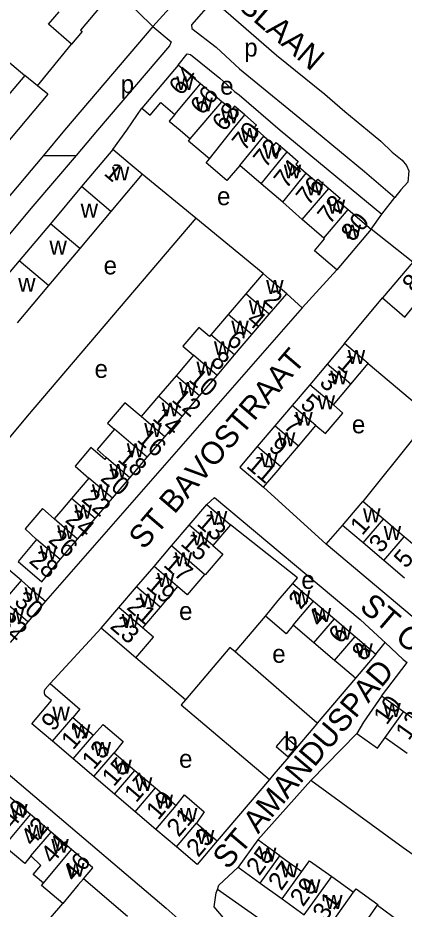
# Model space of a CAD drawing. Extents: x 161258 to 163262, y 380749 to 382054.
# Drawn here: x 163052.1 to 163137.8, y 381577.4 to 381774.9 of the extents above; entities that cross this region are included whole.
import ezdxf

# ---------------------------------------------------------------- set-up
doc = ezdxf.new("R2010")
doc.units = 0
for name, color, linetype in [('BLT_Basislijn', 7, 'Continuous'), ('BLT_Bebouwing', 7, 'Continuous'), ('BLT_Centroide', 7, 'Continuous'), ('BLT_Huisnummer', 7, 'Continuous'), ('BLT_Huisnummer_ tussenligend', 7, 'Continuous'), ('BLT_Huisnummer_reeks', 7, 'Continuous'), ('BLT_Onderverdeling_panden', 7, 'Continuous'), ('BLT_Straatnaam', 7, 'Continuous'), ('BLT_Vlakafsluiter', 7, 'Continuous')]:
    doc.layers.add(name, color=color, linetype=linetype)

msp = doc.modelspace()

# ---------------------------------------------------------------- linework, layer by layer
at = {"layer": 'BLT_Basislijn'}
for p, q in [((163082.1, 381773.01), (163062.51, 381750)), ((163056.49, 381759.86), (163064.05, 381769.1)), ((163056.49, 381759.86), (163053.66, 381762.17)), ((163076.29, 381750), (163079.64, 381754.92)), ((163073.21, 381745.74), (163076.29, 381750)), ((163110.33, 381750), (163132.89, 381731.38)), ((163091.57, 381730.53), (163079.73, 381740.25)), ((163132.89, 381731.38), (163135.76, 381735.11)), ((163130.52, 381728.08), (163132.89, 381731.38)), ((163106.52, 381718.25), (163091.57, 381730.53)), ((163122.86, 381719.1), (163115.21, 381710.67)), ((163115.21, 381710.67), (163111.75, 381713.79)), ((163124.6, 381702.75), (163133, 381712.84)), ((163115.21, 381710.67), (163058.25, 381645.7)), ((163140.28, 381682.2), (163128.63, 381667.72)), ((163106.61, 381670.89), (163120.49, 381658.28)), ((163052.93, 381650.24), (163035.79, 381664.62)), ((163120.49, 381658.28), (163124.16, 381662.45)), ((163157.28, 381627.33), (163120.49, 381658.28)), ((163100.33, 381634.42), (163107.05, 381642.35)), ((163131.54, 381633.92), (163133.58, 381636.48)), ((163118.54, 381618.64), (163100.33, 381634.42)), ((163089.35, 381623.83), (163078.31, 381633.09)), ((163132.79, 381624.62), (163138.48, 381632.04)), ((163127, 381628.59), (163118.54, 381618.64)), ((163118.36, 381618.43), (163111.77, 381610.66)), ((163118.54, 381618.64), (163118.36, 381618.43)), ((163127.31, 381616.36), (163117.14, 381605.96)), ((163111.77, 381610.66), (163108.94, 381607.35)), ((163108.94, 381607.35), (163107.94, 381606.17)), ((163107.94, 381606.17), (163096.36, 381592.56)), ((163117.14, 381605.96), (163105.33, 381592.77)), ((163076.46, 381575.83), (163066.68, 381584.17)), ((163131.58, 381557.2), (163096.41, 381581.77)), ((163053.55, 381568.82), (163062.13, 381578.64))]:
    msp.add_line(p, q, dxfattribs=at)
for points in [[(163095.43, 381778.91), (163093.54, 381780.44), (163092.58, 381780.79), (163090.89, 381781.07), (163088.82, 381780.47), (163082.1, 381773.01)], [(163095.43, 381778.91), (163090.68, 381773.39), (163090.73, 381772.59), (163096.09, 381768.42), (163101.32, 381763.61), (163117.91, 381750)], [(163095.43, 381778.91), (163109.51, 381766.65), (163120.22, 381758.01), (163124.63, 381754.13), (163129.71, 381750)], [(163082.1, 381773.01), (163086.11, 381769.6), (163085.79, 381768.74), (163069.79, 381750)], [(163087.72, 381764.46), (163089.7, 381766.95), (163090.43, 381766.83), (163096.96, 381761.57), (163100.18, 381758.6), (163101.23, 381757.89), (163110.33, 381750)], [(163058.77, 381757.99), (163056.49, 381759.86)], [(163058.77, 381757.99), (162989.39, 381675.54)], [(163062.51, 381750), (163057.84, 381744.45)], [(163069.79, 381750), (163065.05, 381744.45)], [(163117.91, 381750), (163129.03, 381740.88), (163135.76, 381735.11)], [(163129.71, 381750), (163132.65, 381747.6), (163135.16, 381745.16), (163137.36, 381743.36), (163138.32, 381742.17), (163138.87, 381740.99), (163138.61, 381738.52), (163137.07, 381736.82), (163135.76, 381735.11)], [(163065.05, 381744.45), (163055.44, 381733.2), (163000.14, 381667.02), (162999.88, 381666.79), (162998.67, 381667.15), (162995.32, 381669.95)], [(163057.84, 381744.45), (162995.82, 381670.75), (162995.32, 381669.95)], [(163091.57, 381730.53), (163054.18, 381686.63), (163035.79, 381664.62)], [(163129.85, 381698.3), (163143.79, 381686.55), (163140.28, 381682.2)], [(163094.05, 381667.08), (163095.74, 381668.66), (163128.05, 381641.63), (163132.92, 381637.09), (163133.58, 381636.48)], [(163113.11, 381649.61), (163114.13, 381650.83), (163099.29, 381662.59)], [(162982.59, 381655.68), (162982.92, 381655.96), (162983.14, 381656.6), (162984.49, 381658.12), (162987.04, 381658.99), (162989.05, 381658.78), (162990.32, 381658.03), (162999.22, 381650.31), (163015.1, 381637.09), (163026.02, 381627.75), (163057.87, 381600.69), (163085.05, 381577.63), (163092.33, 381571.16), (163092.65, 381569.57), (163088.3, 381564.95)], [(163059.27, 381627.39), (163070.61, 381639.68)], [(163133.58, 381636.48), (163137.6, 381632.77), (163138.48, 381632.04)], [(163100.33, 381634.42), (163099.17, 381635.43), (163089.35, 381623.83)], [(163089.35, 381623.83), (163088.38, 381622.7), (163107.94, 381606.17)], [(163149.49, 381582.65), (163137.61, 381591.03), (163117.14, 381605.96)], [(163096.41, 381581.77), (163096.73, 381582.74), (163100.99, 381586.72)], [(163193.8, 381513.79), (163189.45, 381511.89), (163188.37, 381511.64), (163185.43, 381513.57), (163146.25, 381541.52), (163123.46, 381557.34), (163122.6, 381558.15), (163097.75, 381575.47), (163095.67, 381577.96), (163096.15, 381581.02), (163096.41, 381581.77)]]:
    msp.add_lwpolyline(points, dxfattribs=at)
at = {"layer": 'BLT_Bebouwing'}
for p, q in [((163087.72, 381764.46), (163079.64, 381754.92)), ((163092.67, 381760.27), (163087.72, 381764.46)), ((163053.66, 381762.17), (163046.71, 381753.95)), ((163097.34, 381756.32), (163092.67, 381760.27)), ((163088.11, 381750), (163090.37, 381748.08)), ((163105.19, 381750), (163106.68, 381748.71)), ((163073.21, 381745.74), (163066.28, 381737.52)), ((163106.12, 381738.14), (163101.38, 381742.18)), ((163079.73, 381740.25), (163072.79, 381732.03)), ((163066.28, 381737.52), (163059.35, 381729.3)), ((163110.87, 381734.09), (163106.12, 381738.14)), ((163115.19, 381730.2), (163110.87, 381734.09)), ((163072.79, 381732.03), (163065.86, 381723.81)), ((163125.38, 381732.46), (163130.52, 381728.08)), ((163059.35, 381729.3), (163052.41, 381721.08)), ((163119.97, 381726.12), (163115.19, 381730.2)), ((163130.52, 381728.08), (163122.86, 381719.1)), ((163065.86, 381723.81), (163058.92, 381715.59)), ((163052.41, 381721.08), (163045.48, 381712.86)), ((163139.76, 381720.75), (163133, 381712.84)), ((163106.52, 381718.25), (163102.67, 381713.73)), ((163058.92, 381715.59), (163051.99, 381707.37)), ((163102.67, 381713.73), (163098.8, 381709.2)), ((163107.9, 381709.27), (163111.75, 381713.79)), ((163098.8, 381709.2), (163094.94, 381704.67)), ((163104.03, 381704.74), (163107.9, 381709.27)), ((163100.17, 381700.21), (163104.03, 381704.74)), ((163124.6, 381702.75), (163120.73, 381698.19)), ((163091.07, 381700.14), (163087.21, 381695.61)), ((163096.3, 381695.68), (163100.17, 381700.21)), ((163120.73, 381698.19), (163116.85, 381693.62)), ((163125.98, 381693.73), (163129.85, 381698.3)), ((163087.21, 381695.61), (163083.35, 381691.08)), ((163092.44, 381691.15), (163096.3, 381695.68)), ((163116.85, 381693.62), (163112.98, 381689.05)), ((163122.11, 381689.16), (163125.98, 381693.73)), ((163083.35, 381691.08), (163079.48, 381686.55)), ((163088.57, 381686.62), (163092.44, 381691.15)), ((163112.98, 381689.05), (163109.11, 381684.48)), ((163084.71, 381682.09), (163088.57, 381686.62)), ((163109.11, 381684.48), (163105.23, 381679.91)), ((163114.36, 381680.02), (163118.24, 381684.59)), ((163080.85, 381677.56), (163084.71, 381682.09)), ((163110.49, 381675.46), (163114.36, 381680.02)), ((163076.98, 381673.03), (163080.85, 381677.56)), ((163067.89, 381672.95), (163064.02, 381668.42)), ((163073.12, 381668.49), (163076.98, 381673.03)), ((163069.25, 381663.96), (163073.12, 381668.49)), ((163133.21, 381663.83), (163128.63, 381667.72)), ((163090.14, 381662.51), (163094.05, 381667.08)), ((163094.05, 381667.08), (163099.29, 381662.59)), ((163065.39, 381659.43), (163069.25, 381663.96)), ((163137.79, 381659.95), (163133.21, 381663.83)), ((163086.23, 381657.95), (163090.14, 381662.51)), ((163099.29, 381662.59), (163095.39, 381658.02)), ((163128.73, 381658.56), (163124.16, 381662.45)), ((163142.36, 381656.06), (163137.79, 381659.95)), ((163061.52, 381654.9), (163065.39, 381659.43)), ((163082.33, 381653.38), (163086.23, 381657.95)), ((163133.31, 381654.67), (163128.73, 381658.56)), ((163137.89, 381650.79), (163133.31, 381654.67)), ((163078.42, 381648.81), (163082.33, 381653.38)), ((163049.01, 381645.64), (163052.93, 381650.24)), ((163074.51, 381644.24), (163078.42, 381648.81)), ((163087.57, 381648.89), (163083.67, 381644.32)), ((163113.11, 381649.61), (163117.72, 381645.69)), ((163058.25, 381645.7), (163054.32, 381641.1)), ((163070.61, 381639.68), (163074.51, 381644.24)), ((163083.67, 381644.32), (163079.76, 381639.76)), ((163117.72, 381645.69), (163122.33, 381641.77)), ((163054.32, 381641.1), (163050.4, 381636.5)), ((163117.79, 381636.43), (163113.18, 381640.36)), ((163122.33, 381641.77), (163126.93, 381637.84)), ((163078.31, 381633.09), (163070.61, 381639.68)), ((163122.39, 381632.51), (163117.79, 381636.43)), ((163126.93, 381637.84), (163131.54, 381633.92)), ((163131.54, 381633.92), (163127, 381628.59)), ((163137.65, 381621.17), (163132.79, 381624.62)), ((163142.51, 381617.71), (163137.65, 381621.17)), ((163064.33, 381619.89), (163068.9, 381615.98)), ((163064.41, 381610.72), (163059.83, 381614.62)), ((163133.58, 381615.43), (163138.44, 381611.98)), ((163068.99, 381606.81), (163064.41, 381610.72)), ((163073.48, 381612.08), (163078.06, 381608.18)), ((163073.56, 381602.91), (163068.99, 381606.81)), ((163078.06, 381608.18), (163082.63, 381604.27)), ((163078.14, 381599), (163073.56, 381602.91)), ((163082.63, 381604.27), (163087.21, 381600.37)), ((163054.94, 381598.36), (163050.38, 381602.24)), ((163082.71, 381595.1), (163078.14, 381599)), ((163059.49, 381594.49), (163054.94, 381598.36)), ((163091.79, 381596.46), (163096.36, 381592.56)), ((163064.05, 381590.61), (163059.49, 381594.49)), ((163087.29, 381591.2), (163082.71, 381595.1)), ((163105.33, 381592.77), (163100.99, 381586.72)), ((163110.22, 381589.26), (163115.11, 381585.75)), ((163100.99, 381586.72), (163105.88, 381583.21)), ((163121.73, 381584.64), (163126.6, 381581.16)), ((163105.88, 381583.21), (163110.77, 381579.7)), ((163110.77, 381579.7), (163115.65, 381576.19))]:
    msp.add_line(p, q, dxfattribs=at)
for points in [[(163071.24, 381778.32), (163066.01, 381772.22), (163066.39, 381771.87), (163064.05, 381769.1)], [(163064.05, 381769.1), (163058.94, 381773.51), (163061.33, 381776.24)], [(163047.19, 381767.63), (163049.84, 381765.39), (163053.66, 381762.17)], [(163079.64, 381754.92), (163081.49, 381753.36), (163083.84, 381756.13), (163086.95, 381753.5)], [(163102.44, 381753.39), (163100.16, 381755.32), (163099.58, 381754.63), (163097.34, 381756.32)], [(163086.95, 381753.5), (163085.72, 381752.04), (163088.11, 381750)], [(163105.19, 381750), (163104.55, 381750.55), (163105.07, 381751.16), (163102.44, 381753.39)], [(163106.68, 381748.71), (163108.96, 381746.73), (163109.43, 381747.27), (163111.86, 381745.2)], [(163094.63, 381743.65), (163089.97, 381747.61), (163090.37, 381748.08)], [(163079.73, 381740.25), (163077.04, 381742.52), (163073.21, 381745.74)], [(163111.86, 381745.2), (163114.31, 381743.11), (163113.78, 381742.49), (163116.09, 381740.51)], [(163101.38, 381742.18), (163098.5, 381738.87), (163093.93, 381742.8), (163094.63, 381743.65)], [(163116.09, 381740.51), (163118.26, 381738.67), (163118.68, 381739.16), (163121.09, 381737.11)], [(163121.09, 381737.11), (163123.6, 381734.96), (163123.11, 381734.39), (163125.38, 381732.46)], [(163122.86, 381719.1), (163117.92, 381723.32), (163120.16, 381725.95), (163119.97, 381726.12)], [(163111.75, 381713.79), (163107.95, 381717.04), (163106.52, 381718.25)], [(163133, 381712.84), (163136.8, 381709.59), (163137.93, 381708.62), (163139.8, 381710.85)], [(163094.94, 381704.67), (163094.64, 381704.33), (163092.27, 381706.34), (163088.72, 381702.16), (163091.07, 381700.14)], [(163129.85, 381698.3), (163128.41, 381699.52), (163124.6, 381702.75)], [(163079.48, 381686.55), (163075.89, 381689.6), (163072.03, 381685.08), (163073.58, 381683.76)], [(163118.24, 381684.59), (163120.38, 381682.78), (163124.24, 381687.32), (163122.11, 381689.16)], [(163073.58, 381683.76), (163069.73, 381679.24), (163071.75, 381677.49)], [(163071.75, 381677.49), (163071.43, 381677.06), (163068.34, 381679.7), (163064.83, 381675.58), (163067.89, 381672.95)], [(163105.23, 381679.91), (163101.36, 381675.34), (163106.61, 381670.89)], [(163106.61, 381670.89), (163109.85, 381674.7), (163110.49, 381675.46)], [(163064.02, 381668.42), (163061.69, 381665.62), (163060.16, 381663.89)], [(163124.16, 381662.45), (163127.39, 381666.26), (163128.63, 381667.72)], [(163060.16, 381663.89), (163057.58, 381666.18), (163053.73, 381661.66), (163056.3, 381659.36)], [(163056.3, 381659.36), (163052.19, 381654.46), (163057.44, 381649.98), (163061.52, 381654.9)], [(163095.39, 381658.02), (163097.63, 381656.1), (163093.7, 381651.49), (163093.56, 381651.61)], [(163052.93, 381650.24), (163054.44, 381648.95), (163058.25, 381645.7)], [(163093.56, 381651.61), (163089.69, 381647.08), (163087.57, 381648.89)], [(163107.05, 381642.35), (163109.87, 381645.8), (163113.11, 381649.61)], [(163113.18, 381640.36), (163111.66, 381638.43), (163107.05, 381642.35)], [(163078.31, 381633.09), (163082.21, 381637.66), (163079.76, 381639.76)], [(163127, 381628.59), (163123.19, 381631.83), (163122.39, 381632.51)], [(163059.83, 381614.62), (163055.25, 381618.52), (163059.59, 381623.62), (163058.4, 381624.64), (163058.13, 381624.99), (163058.01, 381625.39), (163058.06, 381625.82), (163058.23, 381626.17), (163059.27, 381627.39)], [(163059.27, 381627.39), (163065.91, 381621.75), (163064.33, 381619.89)], [(163132.79, 381624.62), (163128.78, 381618.84), (163127.31, 381616.36)], [(163068.9, 381615.98), (163071.08, 381618.37), (163075.51, 381614.6), (163073.48, 381612.08)], [(163127.31, 381616.36), (163131.89, 381613.11), (163133.58, 381615.43)], [(163087.21, 381600.37), (163089.08, 381602.74), (163093.46, 381599.01), (163091.79, 381596.46)], [(163055.04, 381589.22), (163053.65, 381587.51), (163049.12, 381591.37), (163050.48, 381593.1)], [(163096.36, 381592.56), (163091.87, 381587.29), (163087.29, 381591.2)], [(163110.22, 381589.26), (163109.4, 381589.85), (163105.33, 381592.77)], [(163066.68, 381584.17), (163068.75, 381586.61), (163064.05, 381590.61)], [(163057.8, 381583.18), (163055.55, 381585.1), (163057.25, 381587.1), (163055.04, 381589.22)], [(163115.11, 381585.75), (163116.84, 381588.13), (163121.73, 381584.64)], [(163062.13, 381578.64), (163057.38, 381582.69), (163057.8, 381583.18)], [(163066.68, 381584.17), (163065.51, 381582.8), (163062.13, 381578.64)], [(163126.6, 381581.16), (163127.15, 381581.93), (163132, 381578.45), (163131.87, 381578.27)], [(163131.87, 381578.27), (163136.72, 381574.79), (163134.66, 381571.72)]]:
    msp.add_lwpolyline(points, dxfattribs=at)
msp.add_lwpolyline([(163111.33, 381615.7), (163109.41, 381613.47), (163112.09, 381611.17), (163114.02, 381613.38)], close=True, dxfattribs=at)
at = {"layer": 'BLT_Onderverdeling_panden'}
for p, q in [((163086.95, 381753.5), (163092.67, 381760.27)), ((163090.37, 381748.08), (163097.34, 381756.32)), ((163099.68, 381750), (163102.44, 381753.39)), ((163094.63, 381743.65), (163099.68, 381750)), ((163101.38, 381742.18), (163106.68, 381748.71)), ((163106.12, 381738.14), (163111.86, 381745.2)), ((163110.87, 381734.09), (163116.09, 381740.51)), ((163072.79, 381732.03), (163066.28, 381737.52)), ((163115.19, 381730.2), (163121.09, 381737.11)), ((163119.97, 381726.12), (163125.38, 381732.46)), ((163065.86, 381723.81), (163059.35, 381729.3)), ((163058.92, 381715.59), (163052.41, 381721.08)), ((163107.9, 381709.27), (163102.67, 381713.73)), ((163104.03, 381704.74), (163098.8, 381709.2)), ((163100.17, 381700.21), (163094.94, 381704.67)), ((163096.3, 381695.68), (163091.07, 381700.14)), ((163125.98, 381693.73), (163120.73, 381698.19)), ((163092.44, 381691.15), (163087.21, 381695.61)), ((163122.11, 381689.16), (163116.85, 381693.62)), ((163088.57, 381686.62), (163083.35, 381691.08)), ((163118.24, 381684.59), (163112.98, 381689.05)), ((163084.71, 381682.09), (163079.48, 381686.55)), ((163080.85, 381677.56), (163073.58, 381683.76)), ((163114.36, 381680.02), (163109.11, 381684.48)), ((163110.49, 381675.46), (163105.23, 381679.91)), ((163076.98, 381673.03), (163071.75, 381677.49)), ((163073.12, 381668.49), (163067.89, 381672.95)), ((163069.25, 381663.96), (163064.02, 381668.42)), ((163065.39, 381659.43), (163060.16, 381663.89)), ((163128.73, 381658.56), (163133.21, 381663.83)), ((163095.39, 381658.02), (163090.14, 381662.51)), ((163133.31, 381654.67), (163137.79, 381659.95)), ((163061.52, 381654.9), (163056.3, 381659.36)), ((163093.56, 381651.61), (163086.23, 381657.95)), ((163087.57, 381648.89), (163082.33, 381653.38)), ((163083.67, 381644.32), (163078.42, 381648.81)), ((163054.32, 381641.1), (163049.01, 381645.64)), ((163079.76, 381639.76), (163074.51, 381644.24)), ((163113.18, 381640.36), (163117.72, 381645.69)), ((163117.79, 381636.43), (163122.33, 381641.77)), ((163122.39, 381632.51), (163126.93, 381637.84)), ((163133.58, 381615.43), (163137.65, 381621.17)), ((163059.83, 381614.62), (163064.33, 381619.89)), ((163064.41, 381610.72), (163068.9, 381615.98)), ((163068.99, 381606.81), (163073.48, 381612.08)), ((163073.56, 381602.91), (163078.06, 381608.18)), ((163078.14, 381599), (163082.63, 381604.27)), ((163082.71, 381595.1), (163087.21, 381600.37)), ((163050.48, 381593.1), (163054.94, 381598.36)), ((163087.29, 381591.2), (163091.79, 381596.46)), ((163055.04, 381589.22), (163059.49, 381594.49)), ((163057.8, 381583.18), (163064.05, 381590.61)), ((163105.88, 381583.21), (163110.22, 381589.26)), ((163110.77, 381579.7), (163115.11, 381585.75)), ((163115.65, 381576.19), (163121.73, 381584.64)), ((163120.54, 381572.68), (163126.6, 381581.16)), ((163125.43, 381569.18), (163131.87, 381578.27))]:
    msp.add_line(p, q, dxfattribs=at)
at = {"layer": 'BLT_Vlakafsluiter'}
for p, q in [((163082.1, 381773.01), (163073.62, 381781.31)), ((163057.84, 381744.45), (163065.05, 381744.45)), ((163139.76, 381720.75), (163130.52, 381728.08))]:
    msp.add_line(p, q, dxfattribs=at)

# ---------------------------------------------------------------- texts
at = {"layer": 'BLT_Centroide'}
for s, p in [('p', (163102.34, 381766.34)), ('p', (163074.95, 381758.24)), ('w', (163087.27, 381758.91)), ('e', (163097, 381757.9)), ('w', (163091.53, 381754.19)), ('w', (163097.22, 381751.55)), ('w', (163101.61, 381747.42)), ('w', (163106.61, 381743.7)), ('w', (163073, 381738.89)), ('w', (163111.11, 381739.33)), ('w', (163116.11, 381735.56)), ('e', (163096.31, 381733.41)), ('w', (163066.06, 381730.67)), ('w', (163120.86, 381731.53)), ('w', (163124.39, 381726.02)), ('w', (163059.14, 381722.45)), ('e', (163071.15, 381718.07)), ('w', (163052.2, 381714.23)), ('w', (163107.2, 381713.75)), ('w', (163103.34, 381709.25)), ('w', (163099.48, 381704.72)), ('w', (163095.62, 381700.19)), ('w', (163125.29, 381698.25)), ('e', (163069.14, 381695.14)), ('w', (163091.75, 381695.66)), ('w', (163121.42, 381693.69)), ('w', (163087.89, 381691.12)), ('w', (163118.61, 381688.19)), ('w', (163084.03, 381686.59)), ('w', (163113.67, 381684.53)), ('e', (163126.21, 381682.86)), ('w', (163080.16, 381682.06)), ('w', (163109.8, 381679.97)), ('w', (163076.3, 381677.53)), ('w', (163105.92, 381675.41)), ('w', (163072.44, 381673)), ('w', (163068.56, 381668.47)), ('w', (163064.7, 381663.94)), ('w', (163094.72, 381662.56)), ('w', (163128.69, 381663.14)), ('w', (163060.84, 381659.41)), ('w', (163133.27, 381659.25)), ('w', (163090.81, 381658)), ('w', (163056.98, 381654.88)), ('w', (163086.91, 381653.41)), ('w', (163083, 381648.84)), ('e', (163115.01, 381648.39)), ('w', (163053.62, 381645.66)), ('w', (163113.14, 381644.98)), ('w', (163079.09, 381644.28)), ('w', (163049.7, 381641.06)), ('e', (163087.89, 381641.5)), ('w', (163117.75, 381641.06)), ('w', (163075.18, 381639.72)), ('w', (163122.36, 381637.14)), ('w', (163126.97, 381633.22)), ('e', (163108.55, 381632.02)), ('w', (163059.8, 381619.2)), ('w', (163133.19, 381620.03)), ('w', (163064.36, 381615.3)), ('b', (163111.2, 381612.59)), ('w', (163068.94, 381611.39)), ('w', (163073.52, 381607.48)), ('e', (163087.89, 381608.76)), ('w', (163078.09, 381603.58)), ('w', (163082.67, 381599.69)), ('w', (163050.44, 381597.67)), ('w', (163088.09, 381596.8)), ('w', (163054.3, 381592.97)), ('w', (163091.83, 381591.88)), ('w', (163059.55, 381589.91)), ('w', (163105.61, 381587.98)), ('w', (163063.06, 381584.61)), ('w', (163110.48, 381584.48)), ('w', (163115.38, 381580.97)), ('w', (163120.27, 381577.47))]:
    msp.add_text(s, height=4, dxfattribs=at).set_placement(p)
at = {"layer": 'BLT_Huisnummer'}
for s, rotation, p in [('64', 50.9195, (163088.37, 381757.48)), ('68', 50.921, (163097.93, 381749.51)), ('72', 50.9216, (163107.08, 381741.47)), ('76', 50.919, (163116.56, 381733.1)), ('80', 49.5327, (163126.44, 381725.1)), ('82', 49.4819, (163140.03, 381713.77)), ('2', 319.5363, (163106.36, 381712.13)), ('6', 319.5417, (163098.2, 381703.04)), ('1', 319.7143, (163122.73, 381697.75)), ('10', 319.5408, (163089.76, 381694.57)), ('5', 319.709, (163114.56, 381688.94)), ('14', 319.5398, (163081.78, 381685.97)), ('18', 319.5335, (163074.05, 381676.86)), ('11', 319.7099, (163102.6, 381675.39)), ('22', 319.5389, (163066.02, 381667.99)), ('13', 319.4581, (163091.61, 381662.63)), ('1', 49.662, (163128.51, 381660.06)), ('28', 319.5255, (163054.41, 381654.32)), ('5', 49.662, (163138.21, 381652.74)), ('17', 319.4581, (163084.22, 381653.48)), ('2', 49.5949, (163114.83, 381643.62)), ('30', 319.5427, (163051.1, 381645.25)), ('23', 319.4581, (163072.37, 381639.82)), ('8', 49.594, (163128.89, 381632.18)), ('10', 54.6176, (163133.94, 381618.04)), ('9', 49.5387, (163060, 381616.63)), ('13', 49.5333, (163068.98, 381608.13)), ('17', 49.5343, (163078.37, 381600.84)), ('40', 49.7593, (163050.98, 381595.02)), ('23', 49.5333, (163092.15, 381588.74)), ('25', 54.3353, (163105.68, 381584.63)), ('46', 49.5914, (163064.67, 381583.3)), ('29', 54.3371, (163115.4, 381577.79))]:
    msp.add_text(s, height=4, rotation=rotation, dxfattribs=at).set_placement(p)
at = {"layer": 'BLT_Huisnummer_ tussenligend'}
for s, rotation, p in [('66', 50.9195, (163093.11, 381753.17)), ('70', 50.921, (163102.37, 381745.2)), ('74', 50.9216, (163111.66, 381736.86)), ('78', 50.919, (163121.3, 381728.95)), ('4', 319.5363, (163102.62, 381707.55)), ('8', 319.5417, (163094.62, 381698.44)), ('3', 319.7143, (163118.8, 381693.74)), ('12', 319.5408, (163086.04, 381690.11)), ('7', 319.709, (163110.82, 381684.21)), ('16', 319.5398, (163078.34, 381681.23)), ('9', 319.709, (163107.53, 381679.47)), ('20', 319.5335, (163070.24, 381672.6)), ('24', 319.5389, (163062.42, 381663.4)), ('26', 319.5389, (163058.69, 381658.95)), ('15', 319.4581, (163088.02, 381658.18)), ('3', 49.662, (163132.67, 381656.13)), ('19', 319.4581, (163080.36, 381648.74)), ('21', 319.4581, (163076.04, 381644.04)), ('4', 49.5949, (163119.12, 381639.74)), ('32', 319.5427, (163047.53, 381640.65)), ('6', 49.5949, (163123.71, 381636)), ('12', 54.6176, (163138.83, 381614.61)), ('11', 49.5387, (163064.4, 381612.53)), ('15', 49.5333, (163073.43, 381604.4)), ('19', 49.5343, (163083.25, 381596.97)), ('21', 49.5343, (163087.81, 381593.22)), ('42', 49.7593, (163055.44, 381591.15)), ('44', 49.7593, (163059.87, 381587.27)), ('27', 54.3353, (163110.55, 381581.32)), ('31', 54.3371, (163120.4, 381574.57))]:
    msp.add_text(s, height=4, rotation=rotation, dxfattribs=at).set_placement(p)
at = {"layer": 'BLT_Huisnummer_reeks'}
msp.add_text('1', height=4, rotation=319.8599, dxfattribs=at).set_placement((163071.01, 381740.24))
at = {"layer": 'BLT_Straatnaam'}
for s, height, rotation, p in [('ST BONIFACIUSLAAN', 4.9999, 319.2576, (163065.25, 381807.8)), ('ST BAVOSTRAAT', 4.9999, 49.398, (163080.08, 381656.89)), ('ST OTGERUSLAAN', 5, 319.4438, (163127.67, 381644.02)), ('ST AMANDUSPAD', 5, 49.8622, (163098.72, 381586))]:
    msp.add_text(s, height=height, rotation=rotation, dxfattribs=at).set_placement(p)

doc.saveas('drawing.dxf')
